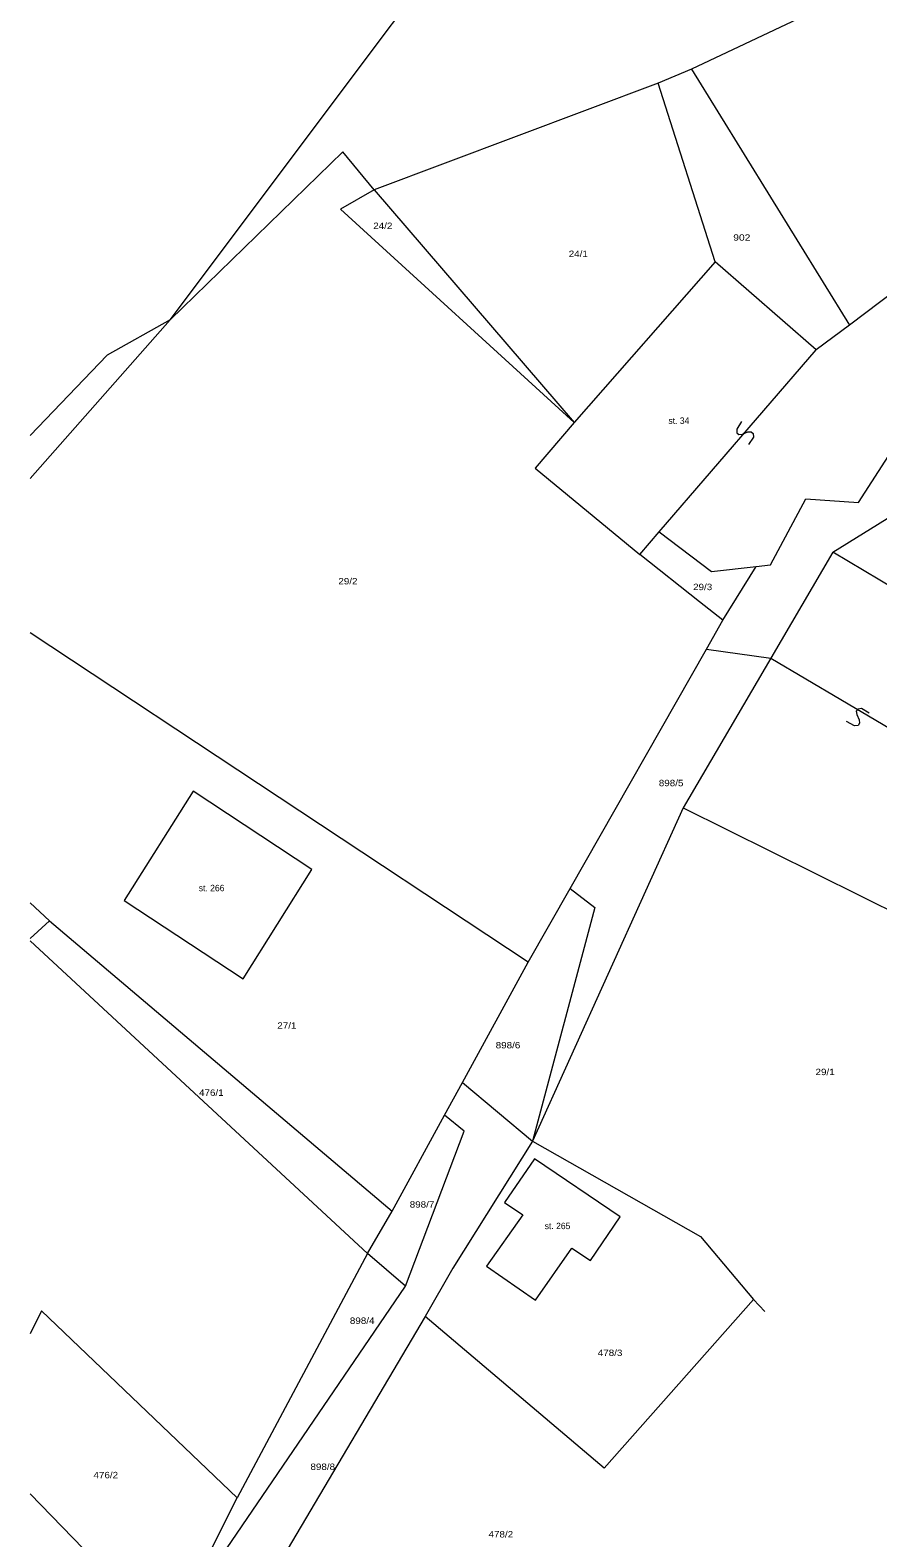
# Model space of a CAD drawing. Extents: x -694702 to -694000, y -1089746 to -1089192.
# Drawn here: x -694637 to -694570.7, y -1089386.1 to -1089268.2 of the extents above; entities that cross this region are included whole.
import ezdxf

# ---------------------------------------------------------------- set-up
doc = ezdxf.new("R2010")
doc.units = 0
doc.header["$LTSCALE"] = 0.2
doc.layers.add('50', color=7, linetype='Continuous', lineweight=13)
doc.layers.add('52', color=7, linetype='Continuous', lineweight=13)

msp = doc.modelspace()

# ---------------------------------------------------------------- linework, layer by layer
at = {"layer": '50'}
for p, q in [((-694585.31, -1089271.23), (-694587.92, -1089272.33)), ((-694585.31, -1089271.23), (-694572.97, -1089291.24)), ((-694587.92, -1089272.33), (-694610.13, -1089280.67)), ((-694583.47, -1089286.31), (-694587.92, -1089272.33)), ((-694610.13, -1089280.67), (-694594.48, -1089298.85)), ((-694560.01, -1089281.46), (-694572.97, -1089291.24)), ((-694583.47, -1089286.31), (-694594.48, -1089298.85)), ((-694637.01, -1089303.25), (-694626.07, -1089290.84)), ((-694587.85, -1089307.42), (-694575.56, -1089293.19)), ((-694574.26, -1089308.99), (-694569.47, -1089306.02)), ((-694574.26, -1089308.99), (-694579.11, -1089317.28)), ((-694582.86, -1089314.32), (-694580.26, -1089310.11)), ((-694584.15, -1089316.58), (-694582.86, -1089314.32)), ((-694598.09, -1089341.07), (-694637.01, -1089315.3)), ((-694594.8, -1089335.29), (-694584.15, -1089316.58)), ((-694584.15, -1089316.58), (-694579.11, -1089317.28)), ((-694579.11, -1089317.28), (-694585.96, -1089328.98)), ((-694579.11, -1089317.28), (-694565.73, -1089325.21)), ((-694585.96, -1089328.98), (-694597.74, -1089355.06)), ((-694635.49, -1089337.83), (-694608.71, -1089360.53)), ((-694637.01, -1089339.38), (-694610.63, -1089363.84)), ((-694603.22, -1089350.47), (-694597.74, -1089355.06)), ((-694608.71, -1089360.53), (-694604.61, -1089353.02)), ((-694610.63, -1089363.84), (-694608.71, -1089360.53)), ((-694610.63, -1089363.84), (-694620.82, -1089382.95)), ((-694607.67, -1089366.38), (-694610.63, -1089363.84)), ((-694626.27, -1089393.68), (-694607.67, -1089366.38)), ((-694580.48, -1089367.44), (-694579.58, -1089368.37)), ((-694606.14, -1089368.76), (-694617.27, -1089387.58)), ((-694626.27, -1089393.68), (-694637.01, -1089382.62)), ((-694626.27, -1089393.68), (-694620.82, -1089382.95))]:
    msp.add_line(p, q, dxfattribs=at)
for points in [[(-694626.07, -1089290.84), (-694591.39, -1089244.57), (-694570.65, -1089212.72), (-694562.928, -1089202.206)], [(-694551.73, -1089260.17), (-694558.74, -1089262.74), (-694568.25, -1089263.15), (-694585.31, -1089271.23)], [(-694610.13, -1089280.67), (-694612.58, -1089277.69), (-694626.07, -1089290.84)], [(-694610.13, -1089280.67), (-694612.75, -1089282.19), (-694594.48, -1089298.85)], [(-694580.26, -1089310.11), (-694579.15, -1089309.98), (-694576.37, -1089304.83), (-694572.27, -1089305.11), (-694557.85, -1089282.77), (-694560.01, -1089281.46)], [(-694572.97, -1089291.24), (-694575.56, -1089293.19), (-694583.47, -1089286.31)], [(-694626.07, -1089290.84), (-694630.99, -1089293.6), (-694637.01, -1089299.88)], [(-694594.48, -1089298.85), (-694597.53, -1089302.44), (-694589.34, -1089309.17)], [(-694589.34, -1089309.17), (-694587.85, -1089307.42), (-694583.76, -1089310.52), (-694580.26, -1089310.11)], [(-694582.86, -1089314.32), (-694584.68, -1089312.89), (-694589.34, -1089309.17)], [(-694555.66, -1089323.1), (-694557.44, -1089321.7), (-694556.26, -1089319.73), (-694560.8, -1089317.02), (-694574.26, -1089308.99)], [(-694585.96, -1089328.98), (-694565.18, -1089339.31), (-694558.81, -1089328.46), (-694555.66, -1089323.1)], [(-694603.22, -1089350.47), (-694598.09, -1089341.07), (-694594.8, -1089335.29)], [(-694594.8, -1089335.29), (-694592.86, -1089336.77), (-694597.74, -1089355.06)], [(-694637.01, -1089336.41), (-694635.49, -1089337.83), (-694637.01, -1089339.2)], [(-694607.67, -1089366.38), (-694603.09, -1089354.28), (-694604.61, -1089353.02), (-694603.22, -1089350.47)], [(-694597.74, -1089355.06), (-694603.96, -1089364.97), (-694606.14, -1089368.76)], [(-694597.74, -1089355.06), (-694584.6, -1089362.51), (-694580.48, -1089367.44)], [(-694580.48, -1089367.44), (-694592.14, -1089380.62), (-694606.14, -1089368.76)], [(-694620.82, -1089382.95), (-694636.12, -1089368.32), (-694637.01, -1089370.12)]]:
    msp.add_lwpolyline(points, dxfattribs=at)
for points in [[(-694624.26, -1089327.68), (-694629.66, -1089336.23), (-694620.37, -1089342.37), (-694614.99, -1089333.81)], [(-694594.66, -1089363.41), (-694593.22, -1089364.39), (-694590.9, -1089360.96), (-694597.59, -1089356.43), (-694599.92, -1089359.86), (-694598.51, -1089360.81), (-694601.33, -1089364.82), (-694597.52, -1089367.49)]]:
    msp.add_lwpolyline(points, close=True, dxfattribs=at)
at = {"layer": '52'}
for points in [[(-694581.396, -1089298.792), (-694581.776, -1089299.38), (-694581.762, -1089299.665), (-694581.612, -1089299.801), (-694581.329, -1089299.774), (-694580.916, -1089299.604), (-694580.638, -1089299.585), (-694580.483, -1089299.713), (-694580.461, -1089300.004), (-694580.849, -1089300.586)], [(-694571.425, -1089321.58), (-694572.034, -1089321.234), (-694572.318, -1089321.265), (-694572.445, -1089321.422), (-694572.401, -1089321.703), (-694572.209, -1089322.106), (-694572.174, -1089322.381), (-694572.292, -1089322.544), (-694572.582, -1089322.583), (-694573.185, -1089322.228)]]:
    msp.add_lwpolyline(points, dxfattribs=at)

# ---------------------------------------------------------------- texts
for s, width, p in [('24/2', 1.15, (-694610.19, -1089283.73)), ('902', 1.2, (-694582.05, -1089284.65)), ('24/1', 1.15, (-694594.91, -1089285.92)), ('29/2', 1.15, (-694612.92, -1089311.52)), ('29/3', 1.15, (-694585.19, -1089311.97)), ('898/5', 1.15, (-694587.87, -1089327.3)), ('27/1', 1.15, (-694617.69, -1089346.26)), ('898/6', 1.15, (-694600.62, -1089347.8)), ('29/1', 1.15, (-694575.62, -1089349.89)), ('476/1', 1.15, (-694623.81, -1089351.51)), ('898/7', 1.15, (-694607.34, -1089360.25)), ('898/4', 1.15, (-694612.02, -1089369.34)), ('478/3', 1.15, (-694592.64, -1089371.85)), ('898/8', 1.15, (-694615.1, -1089380.76)), ('476/2', 1.15, (-694632.06, -1089381.41)), ('478/2', 1.15, (-694601.18, -1089386.04))]:
    msp.add_text(s, height=0.5, dxfattribs=dict(at, width=width)).set_placement(p)
for s, p in [('st. 34', (-694587.12, -1089298.97)), ('st. 266', (-694623.83, -1089335.51)), ('st. 265', (-694596.79, -1089361.93))]:
    msp.add_text(s, height=0.5, dxfattribs=at).set_placement(p)

doc.saveas('drawing.dxf')
